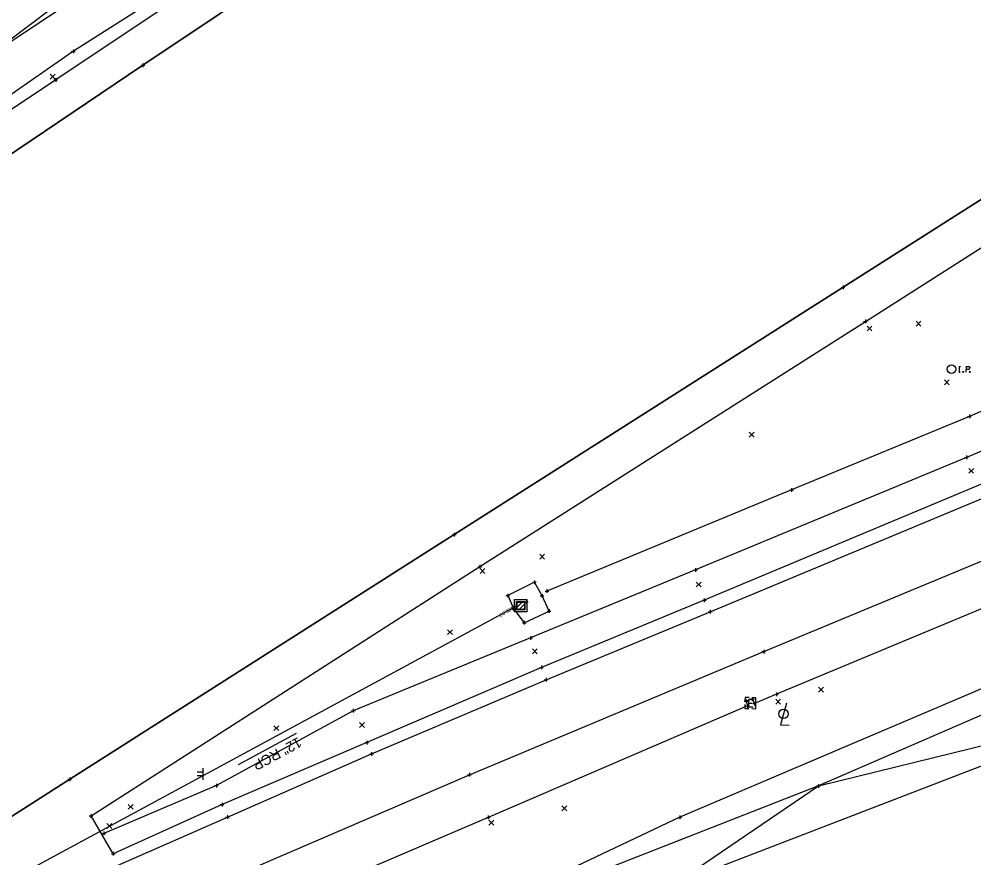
# Model space of a CAD drawing. Extents: x 142461 to 147261, y 511126 to 514697.
# Drawn here: x 144403.5 to 144664.8, y 512765.9 to 512995.5 of the extents above; entities that cross this region are included whole.
import ezdxf

# ---------------------------------------------------------------- set-up
doc = ezdxf.new("R2010")
doc.units = 0
for name, color, linetype in [('DR_X_Cells', 7, 'Continuous'), ('DR_X_Ditch', 7, 'Continuous'), ('DR_X_Elev_Flow', 7, 'Continuous'), ('DR_X_Storm_Sewer', 7, 'Continuous'), ('DR_X_Text', 7, 'Continuous'), ('GK_Drainage_Nodes', 7, 'Continuous'), ('LT_X_Poles', 7, 'Continuous'), ('PM_X_Surveyed_Line', 7, 'Continuous'), ('PV_X_EOP', 7, 'Continuous'), ('PV_X_Shoulder', 7, 'Continuous'), ('RD_X_Concrete_Pad', 7, 'Continuous'), ('RD_X_Fence', 7, 'Continuous'), ('SC_Scratch1', 7, 'Continuous'), ('SN_X_Public', 7, 'Continuous'), ('SV_P_Mon_Cells_Set', 7, 'Continuous'), ('SV_X_Original_Ground', 7, 'Continuous'), ('SV_X_Random_Point', 7, 'Continuous'), ('SV_X_Shot_Marker', 7, 'Continuous'), ('SV_X_Toe_of_Slope', 7, 'Continuous'), ('SV_X_Top_of_Bank', 7, 'Continuous'), ('UT_X_Electric_Cells', 7, 'Continuous'), ('VG_X_Tree_Line_Lt', 7, 'Continuous'), ('VG_X_Tree_Line_Rt', 7, 'Continuous')]:
    doc.layers.add(name, color=color, linetype=linetype)

msp = doc.modelspace()

# ---------------------------------------------------------------- linework, layer by layer
at = {"layer": 'DR_X_Cells'}
for p, q in [((144539.58, 512834.31), (144541.34, 512836.07)), ((144539.58, 512835.44), (144540.21, 512836.07)), ((144540.18, 512833.78), (144541.87, 512835.47)), ((144541.31, 512833.78), (144541.87, 512834.34))]:
    msp.add_line(p, q, dxfattribs=at)
for points in [[(144539.06, 512836.59), (144542.39, 512836.59), (144542.39, 512833.26), (144539.06, 512833.26)], [(144539.58, 512836.07), (144541.87, 512836.07), (144541.87, 512833.78), (144539.58, 512833.78)], [(144539.73, 512835.92), (144541.73, 512835.92), (144541.73, 512833.92), (144539.73, 512833.92)]]:
    msp.add_lwpolyline(points, close=True, dxfattribs=at)
at = {"layer": 'DR_X_Ditch'}
msp.add_lwpolyline([(144155.19, 512824.55), (144192.53, 512847.33), (144223.15, 512869.62), (144254.62, 512891.25), (144280.41, 512905.71), (144318.49, 512934.86), (144358.21, 512961.23), (144398.77, 512988.26), (144440.87, 513020.08), (144475.09, 513048.33), (144506.87, 513067.96), (144540.61, 513089.99), (144584.43, 513110.27), (144621.43, 513136.23), (144661.42, 513162.19), (144708.91, 513198.2), (144729.29, 513226.26), (144727.57, 513229.5), (144738.49, 513243.53), (144758.32, 513273.99)], dxfattribs=at)
at = {"layer": 'DR_X_Elev_Flow'}
for p, q in [((144541.79, 512836.03), (144542.79, 512836.03)), ((144542.29, 512836.53), (144542.29, 512835.53)), ((144542.29, 512836.03), (144542.29, 512836.03))]:
    msp.add_line(p, q, dxfattribs=at)
at = {"layer": 'DR_X_Storm_Sewer'}
msp.add_line((144539.42, 512834.67), (144405.18, 512762.11), dxfattribs=at)
at = {"layer": 'DR_X_Text'}
msp.add_line((144463.5, 512791.48), (144479.38, 512800.06), dxfattribs=at)
at = {"layer": 'GK_Drainage_Nodes'}
for p, q in [((144539.73, 512834.92), (144539.73, 512834.92)), ((144540.73, 512836.59), (144540.73, 512836.59)), ((144540.73, 512835.92), (144540.73, 512835.92)), ((144540.73, 512834.92), (144540.73, 512834.92)), ((144540.73, 512834.92), (144540.73, 512834.92)), ((144540.73, 512834.92), (144540.73, 512834.92)), ((144541.73, 512834.92), (144541.73, 512834.92)), ((144540.73, 512833.92), (144540.73, 512833.92)), ((144540.73, 512833.26), (144540.73, 512833.26))]:
    msp.add_line(p, q, dxfattribs=at)
at = {"layer": 'LT_X_Poles'}
msp.add_lwpolyline([(144613.47, 512808.27), (144611.84, 512802.3), (144614.2, 512802.27)], dxfattribs=at)
msp.add_circle((144612.66, 512805.32), 1.3, dxfattribs=at)
at = {"layer": 'PM_X_Surveyed_Line'}
for points in [[(145244.8, 513598.91), (145189.1, 513544.15), (145118.95, 513483.86), (145022.54, 513402.94), (144981.98, 513369.93), (144853.86, 513268.93), (144843.13, 513260.73), (144805.16, 513232.38), (144766.25, 513204.67), (144725.33, 513176.3), (144684.91, 513148.47), (144644.29, 513120.74), (144603.48, 513093.63), (144562.1, 513066.23), (144520.96, 513039), (144479.14, 513010.91), (144437.33, 512982.92), (144395.18, 512954.5), (144353.44, 512926.48), (144318.54, 512903.34), (144276.1, 512875.34), (144232.02, 512845.98), (144188.92, 512817.39), (144145.08, 512788.07)], [(144079.63, 512572.09), (144161.19, 512623.62), (144232.68, 512669.39), (144303.71, 512715.03), (144372.67, 512758.92), (144417.33, 512787.4), (144522.55, 512854.42), (144628.96, 512922.1), (144693.88, 512963.42), (144795.96, 513028.33), (144851.81, 513063.86), (144912.86, 513102.61), (144997.35, 513156.18), (145071.95, 513203.81), (145158.73, 513259.05)], [(144161.19, 512623.62), (144234.91, 512664.76), (144308.58, 512704.75), (144382.31, 512742.08), (144431.43, 512764.26), (144460.46, 512777.08), (144499.91, 512794.34), (144547.7, 512814.68), (144592.59, 512833.3), (144667.23, 512864.35), (144709.98, 512882.09), (144731.76, 512891.11), (144777.76, 512910.35), (144847.49, 512940.98), (144877.97, 512956.57), (144906.17, 512973.31), (144970.66, 513014.86), (145008.54, 513039.23), (145047.45, 513063.87), (145126.17, 513113.66), (145208.14, 513166.05), (145269.39, 513204.92)], [(144107.76, 512571.5), (144171, 512608.92), (144233.75, 512643.91), (144295.17, 512677.9), (144371.33, 512718.45), (144406.15, 512735.4), (144436.98, 512749.5), (144470.36, 512764.31), (144526.68, 512788.67), (144607.27, 512822.36), (144672.99, 512849.66), (144737.98, 512876.7), (144783.51, 512895.57), (144854.72, 512926.92), (144917.44, 512958.12), (144951.07, 512971.35), (144954.37, 512973.11)]]:
    msp.add_lwpolyline(points, dxfattribs=at)
at = {"layer": 'PV_X_EOP'}
for p, q in [((144490.96, 513030.72), (144413.5, 512978.9)), ((144413.5, 512978.9), (144329.88, 512923)), ((144678.33, 512838.89), (144610.7, 512810.67)), ((144610.7, 512810.67), (144604.72, 512808.14)), ((144604.13, 512809.39), (144602.41, 512808.77)), ((144602.41, 512808.77), (144602.81, 512807.48)), ((144604.72, 512808.14), (144604.13, 512809.39)), ((144602.81, 512807.48), (144531.86, 512776.95)), ((144531.86, 512776.95), (144475.53, 512752.94))]:
    msp.add_line(p, q, dxfattribs=at)
for points in [[(144423.14, 512777.38), (144529.59, 512845.63), (144635.07, 512912.79), (144699.77, 512953.97), (144801.25, 513018.67), (144857.84, 513054.39), (144918.27, 513092.86), (145002.41, 513146.27), (145077.85, 513194.39), (145164.32, 513249.25)], [(144911.02, 512977.55), (144906.51, 512974.41), (144900.33, 512983.57), (144872.27, 512967.78), (144841.71, 512952.09), (144773.16, 512922.36), (144725.8, 512902.13), (144705.18, 512893.45), (144708.57, 512885.5), (144665.93, 512867.84), (144590.97, 512836.44), (144546.42, 512818.03), (144498.61, 512797.46), (144459.01, 512780.5), (144429.23, 512767.01), (144423.14, 512777.38)]]:
    msp.add_lwpolyline(points, dxfattribs=at)
at = {"layer": 'PV_X_Shoulder'}
msp.add_lwpolyline([(144705.18, 512893.45), (144662.72, 512875.53), (144588.59, 512844.72), (144543.46, 512826.1), (144494.9, 512806.19), (144457.46, 512785.68), (144426.6, 512772.57)], dxfattribs=at)
at = {"layer": 'RD_X_Concrete_Pad'}
msp.add_lwpolyline([(144541.72, 512830.26), (144548.49, 512833.47), (144546.57, 512837.62), (144544.51, 512841.36), (144537.19, 512837.72), (144538.83, 512834)], close=True, dxfattribs=at)
at = {"layer": 'RD_X_Fence'}
msp.add_lwpolyline([(143478.94, 512019.34), (143711.38, 512177.16), (144427.62, 512645.69), (144477.47, 512681.98), (144582.58, 512758.57), (144706.18, 512806.24), (144763.41, 512828.73), (144839.36, 512854.89), (144928.89, 512885.13), (144926.13, 512699.9), (144921.71, 512476.45), (144997.12, 512524.34), (145097.9, 512588.02), (145394.3, 512776.52), (145562.04, 512882.95), (145736.06, 512993.23), (145625.27, 513165.45), (145520.47, 513331.41), (145754.83, 513482.5), (146985.53, 514272.72), (147146.04, 514395.19)], dxfattribs=at)
at = {"layer": 'SN_X_Public'}
for p, q in [((144453.78, 512790.45), (144453.78, 512787.25)), ((144453.78, 512789.33), (144452.18, 512789.33)), ((144453.78, 512788.37), (144452.18, 512788.37)), ((144453.78, 512788.85), (144453.78, 512788.85))]:
    msp.add_line(p, q, dxfattribs=at)
at = {"layer": 'SV_P_Mon_Cells_Set'}
for p, q in [((144660.66, 512900.46), (144661.06, 512900.46)), ((144660.84, 512898.86), (144660.86, 512900.46)), ((144662.69, 512899.68), (144663.34, 512899.67)), ((144660.64, 512898.86), (144661.04, 512898.86))]:
    msp.add_line(p, q, dxfattribs=at)
msp.add_lwpolyline([(144662.68, 512898.84), (144662.7, 512900.44), (144663.35, 512900.44)], dxfattribs=at)
for centre, radius in [((144658.65, 512899.69), 1.2), ((144661.81, 512898.96), 0.14), ((144663.65, 512898.94), 0.14)]:
    msp.add_circle(centre, radius, dxfattribs=at)
for points in [[(144663.34, 512899.67), (144663.41, 512899.68), (144663.59, 512899.78), (144663.66, 512899.96), (144663.67, 512900.05), (144663.67, 512900.05), (144663.67, 512900.05)], [(144663.35, 512900.44), (144663.48, 512900.4), (144663.61, 512900.29), (144663.66, 512900.15), (144663.67, 512900.05)]]:
    msp.add_open_spline(points, degree=2, dxfattribs=at)
at = {"layer": 'SV_X_Original_Ground'}
for points in [[(145158.73, 513259.05), (145071.95, 513203.81), (144997.35, 513156.18), (144912.86, 513102.61), (144851.81, 513063.86), (144795.96, 513028.33), (144693.88, 512963.42), (144628.96, 512922.1), (144522.55, 512854.42), (144417.33, 512787.4), (144372.67, 512758.92), (144303.71, 512715.03), (144232.68, 512669.39), (144161.19, 512623.62), (144079.63, 512572.09)], [(144145.08, 512788.07), (144188.92, 512817.39), (144232.02, 512845.98), (144276.1, 512875.34), (144318.54, 512903.34), (144353.44, 512926.48), (144395.18, 512954.5), (144437.33, 512982.92), (144479.14, 513010.91), (144520.96, 513039), (144562.1, 513066.23), (144603.48, 513093.63), (144644.29, 513120.74), (144684.91, 513148.47), (144725.33, 513176.3), (144766.25, 513204.67), (144805.16, 513232.38)], [(144146.46, 512461.37), (144182.31, 512479.61), (144214, 512505.32), (144287, 512560.13), (144347.93, 512601.69), (144364.84, 512611.91), (144427.62, 512645.69), (144477.47, 512681.98), (144514.41, 512743.19), (144582.58, 512758.57), (144622.22, 512785.58), (144706.18, 512806.24)]]:
    msp.add_lwpolyline(points, dxfattribs=at)
at = {"layer": 'SV_X_Random_Point'}
for p, q in [((144411.97, 512980.45), (144413.29, 512979.11)), ((144411.96, 512979.12), (144413.3, 512980.44)), ((144648.95, 512911.51), (144650.28, 512912.84)), ((144648.95, 512912.84), (144650.28, 512911.51)), ((144635.51, 512910.17), (144636.86, 512911.49)), ((144635.52, 512911.51), (144636.84, 512910.16)), ((144656.71, 512895.42), (144658.04, 512896.76)), ((144656.71, 512896.76), (144658.04, 512895.42)), ((144603.3, 512881.12), (144604.64, 512882.46)), ((144603.3, 512882.46), (144604.64, 512881.12)), ((144663.37, 512871.19), (144664.72, 512872.51)), ((144663.38, 512872.53), (144664.7, 512871.18)), ((144545.93, 512847.66), (144547.26, 512849)), ((144545.93, 512849), (144547.26, 512847.66)), ((144529.61, 512843.78), (144530.96, 512845.1)), ((144529.62, 512845.12), (144530.94, 512843.77)), ((144588.77, 512840.09), (144590.12, 512841.41)), ((144588.79, 512841.42), (144590.1, 512840.07)), ((144520.72, 512827.04), (144522.05, 512828.37)), ((144520.72, 512828.37), (144522.05, 512827.04)), ((144543.93, 512821.8), (144545.28, 512823.12)), ((144543.94, 512823.13), (144545.26, 512821.79)), ((144622.25, 512811.27), (144623.58, 512812.6)), ((144622.25, 512812.6), (144623.58, 512811.27)), ((144610.52, 512808.02), (144611.87, 512809.35)), ((144610.54, 512809.36), (144611.86, 512808.01)), ((144496.61, 512801.63), (144497.96, 512802.95)), ((144496.63, 512802.96), (144497.95, 512801.61)), ((144473.16, 512800.74), (144474.5, 512802.07)), ((144473.16, 512802.07), (144474.5, 512800.74)), ((144433.31, 512779.2), (144434.64, 512780.53)), ((144433.31, 512780.53), (144434.64, 512779.2)), ((144552, 512778.77), (144553.34, 512780.11)), ((144552, 512780.11), (144553.34, 512778.77)), ((144427.47, 512773.97), (144428.81, 512775.29)), ((144427.48, 512775.31), (144428.8, 512773.96)), ((144532, 512774.88), (144533.35, 512776.2)), ((144532.02, 512776.21), (144533.34, 512774.86))]:
    msp.add_line(p, q, dxfattribs=at)
at = {"layer": 'SV_X_Shot_Marker'}
for p, q in [((144417.81, 512986.73), (144418.81, 512986.73)), ((144418.31, 512987.23), (144418.31, 512986.23)), ((144418.31, 512986.73), (144418.31, 512986.73)), ((144437.33, 512983.42), (144437.33, 512982.42)), ((144436.83, 512982.92), (144437.83, 512982.92)), ((144437.33, 512982.92), (144437.33, 512982.92)), ((144413, 512978.91), (144414, 512978.9)), ((144413.51, 512979.4), (144413.5, 512978.4)), ((144413.5, 512978.9), (144413.5, 512978.9)), ((144628.46, 512922.1), (144629.46, 512922.09)), ((144628.96, 512922.6), (144628.95, 512921.6)), ((144628.96, 512922.1), (144628.96, 512922.1)), ((144634.57, 512912.79), (144635.57, 512912.78)), ((144635.08, 512913.29), (144635.07, 512912.29)), ((144635.07, 512912.79), (144635.07, 512912.79)), ((144663.06, 512886.77), (144664.06, 512886.77)), ((144663.56, 512887.27), (144663.56, 512886.27)), ((144663.56, 512886.77), (144663.56, 512886.77)), ((144662.73, 512876.03), (144662.72, 512875.03)), ((144662.22, 512875.54), (144663.22, 512875.53)), ((144662.72, 512875.53), (144662.72, 512875.53)), ((144614.36, 512866.63), (144615.36, 512866.63)), ((144614.86, 512867.13), (144614.86, 512866.13)), ((144614.86, 512866.63), (144614.86, 512866.63)), ((144522.05, 512854.43), (144523.05, 512854.42)), ((144522.55, 512854.92), (144522.54, 512853.92)), ((144522.55, 512854.42), (144522.55, 512854.42)), ((144529.09, 512845.63), (144530.09, 512845.62)), ((144529.59, 512846.13), (144529.58, 512845.13)), ((144529.59, 512845.63), (144529.59, 512845.63)), ((144588.09, 512844.73), (144589.09, 512844.72)), ((144588.59, 512845.22), (144588.58, 512844.22)), ((144588.59, 512844.72), (144588.59, 512844.72)), ((144544.01, 512841.36), (144545.01, 512841.36)), ((144544.51, 512841.86), (144544.51, 512840.86)), ((144544.51, 512841.36), (144544.51, 512841.36)), ((144547.92, 512839.43), (144547.92, 512838.43)), ((144536.69, 512837.72), (144537.69, 512837.72)), ((144537.19, 512838.22), (144537.19, 512837.22)), ((144537.19, 512837.72), (144537.19, 512837.72)), ((144546.07, 512837.62), (144547.07, 512837.62)), ((144546.57, 512838.12), (144546.57, 512837.12)), ((144546.57, 512837.62), (144546.57, 512837.62)), ((144547.42, 512838.93), (144548.42, 512838.93)), ((144547.92, 512838.93), (144547.92, 512838.93)), ((144590.97, 512836.94), (144590.96, 512835.94)), ((144538.83, 512834.5), (144538.83, 512833.5)), ((144538.92, 512834.67), (144539.92, 512834.67)), ((144539.42, 512835.17), (144539.42, 512834.17)), ((144539.42, 512834.67), (144539.42, 512834.67)), ((144590.47, 512836.45), (144591.47, 512836.44)), ((144590.97, 512836.44), (144590.97, 512836.44)), ((144538.33, 512834), (144539.33, 512834)), ((144538.83, 512834), (144538.83, 512834)), ((144547.99, 512833.47), (144548.99, 512833.47)), ((144548.49, 512833.97), (144548.49, 512832.97)), ((144548.49, 512833.47), (144548.49, 512833.47)), ((144592.09, 512833.31), (144593.09, 512833.29)), ((144592.59, 512833.8), (144592.58, 512832.8)), ((144592.59, 512833.3), (144592.59, 512833.3)), ((144541.22, 512830.26), (144542.22, 512830.26)), ((144541.72, 512830.76), (144541.72, 512829.76)), ((144541.72, 512830.26), (144541.72, 512830.26)), ((144543.47, 512826.6), (144543.46, 512825.6)), ((144542.96, 512826.1), (144543.96, 512826.09)), ((144543.46, 512826.1), (144543.46, 512826.1)), ((144606.77, 512822.36), (144607.77, 512822.35)), ((144607.27, 512822.86), (144607.26, 512821.86)), ((144607.27, 512822.36), (144607.27, 512822.36)), ((144546.43, 512818.53), (144546.42, 512817.53)), ((144545.92, 512818.04), (144546.92, 512818.02)), ((144546.42, 512818.03), (144546.42, 512818.03)), ((144547.2, 512814.69), (144548.2, 512814.68)), ((144547.71, 512815.18), (144547.7, 512814.18)), ((144547.7, 512814.68), (144547.7, 512814.68)), ((144610.2, 512810.67), (144611.2, 512810.66)), ((144610.71, 512811.17), (144610.7, 512810.17)), ((144610.7, 512810.67), (144610.7, 512810.67)), ((144601.91, 512808.77), (144602.91, 512808.76)), ((144602.42, 512809.27), (144602.41, 512808.27)), ((144602.41, 512808.77), (144602.41, 512808.77)), ((144603.63, 512809.39), (144604.63, 512809.38)), ((144604.13, 512809.89), (144604.12, 512808.89)), ((144604.13, 512809.39), (144604.13, 512809.39)), ((144604.22, 512808.15), (144605.22, 512808.14)), ((144604.72, 512808.64), (144604.71, 512807.64)), ((144604.72, 512808.14), (144604.72, 512808.14)), ((144494.4, 512806.2), (144495.4, 512806.19)), ((144494.91, 512806.69), (144494.9, 512805.69)), ((144494.9, 512806.19), (144494.9, 512806.19)), ((144602.31, 512807.48), (144603.31, 512807.47)), ((144602.82, 512807.98), (144602.81, 512806.98)), ((144602.81, 512807.48), (144602.81, 512807.48)), ((144498.62, 512797.96), (144498.6, 512796.96)), ((144498.11, 512797.46), (144499.11, 512797.45)), ((144498.61, 512797.46), (144498.61, 512797.46)), ((144499.41, 512794.35), (144500.41, 512794.34)), ((144499.91, 512794.84), (144499.9, 512793.84)), ((144499.91, 512794.34), (144499.91, 512794.34)), ((144416.83, 512787.41), (144417.83, 512787.4)), ((144417.33, 512787.9), (144417.32, 512786.9)), ((144417.33, 512787.4), (144417.33, 512787.4)), ((144526.18, 512788.67), (144527.18, 512788.66)), ((144526.68, 512789.17), (144526.67, 512788.17)), ((144526.68, 512788.67), (144526.68, 512788.67)), ((144456.96, 512785.68), (144457.96, 512785.67)), ((144457.46, 512786.18), (144457.45, 512785.18)), ((144457.46, 512785.68), (144457.46, 512785.68)), ((144621.72, 512785.58), (144622.72, 512785.58)), ((144622.22, 512786.08), (144622.22, 512785.08)), ((144622.22, 512785.58), (144622.22, 512785.58)), ((144458.51, 512780.51), (144459.51, 512780.5)), ((144459.01, 512781), (144459, 512780)), ((144459.01, 512780.5), (144459.01, 512780.5)), ((144422.64, 512777.38), (144423.64, 512777.37)), ((144423.14, 512777.88), (144423.13, 512776.88)), ((144423.14, 512777.38), (144423.14, 512777.38)), ((144459.96, 512777.08), (144460.96, 512777.07)), ((144460.46, 512777.58), (144460.45, 512776.58)), ((144460.46, 512777.08), (144460.46, 512777.08)), ((144531.36, 512776.95), (144532.36, 512776.94)), ((144531.87, 512777.45), (144531.86, 512776.45)), ((144531.86, 512776.95), (144531.86, 512776.95)), ((144583.76, 512777), (144584.76, 512776.99)), ((144584.27, 512777.5), (144584.26, 512776.5)), ((144584.26, 512777), (144584.26, 512777)), ((144426.1, 512772.57), (144427.1, 512772.56)), ((144426.61, 512773.07), (144426.6, 512772.07)), ((144426.6, 512772.57), (144426.6, 512772.57)), ((144428.73, 512767.01), (144429.73, 512767)), ((144429.24, 512767.51), (144429.23, 512766.51)), ((144429.23, 512767.01), (144429.23, 512767.01))]:
    msp.add_line(p, q, dxfattribs=at)
at = {"layer": 'SV_X_Toe_of_Slope'}
msp.add_lwpolyline([(145536.33, 513468.51), (145487.34, 513431.87), (145445.96, 513398.71), (145400.54, 513359.53), (145354.59, 513321.64), (145305.79, 513280.24), (145266.24, 513246.77), (145228.58, 513220.65), (145175.08, 513189.66), (145126.31, 513155.94), (145081.98, 513127.67), (145034.97, 513097.1), (144983.36, 513063.49), (144934.41, 513028.84), (144889.77, 512994.77), (144833.63, 512962.42), (144772.97, 512934.59), (144716.73, 512910.04), (144663.56, 512886.77), (144614.86, 512866.63), (144547.92, 512838.93)], dxfattribs=at)
at = {"layer": 'SV_X_Top_of_Bank'}
for points in [[(144938.7, 513352.73), (144903.82, 513325.51), (144869.31, 513299.61), (144834.32, 513271.97), (144798.6, 513244.63), (144760.27, 513217.79), (144723.38, 513192.87), (144685.94, 513168.03), (144649.73, 513141.54), (144613.86, 513117.07), (144574.64, 513090.25), (144534.95, 513065.21), (144496.59, 513038.93), (144457.47, 513011.69), (144418.31, 512986.73), (144376.29, 512957.57), (144335.22, 512930.35), (144295.66, 512903.81), (144255.35, 512877.84), (144213.89, 512852), (144187.53, 512836.11), (144149.1, 512812.16)], [(144733.96, 512831.9), (144682.77, 512811.9), (144622.22, 512785.58), (144559.34, 512760.99), (144514.41, 512743.19), (144445.8, 512704.27), (144422.79, 512686.96), (144404.36, 512674.95), (144403.17, 512671), (144396.75, 512657.34), (144383.89, 512640.78), (144355.33, 512621.72), (144335.88, 512616.13), (144292.97, 512579.83), (144267.67, 512559.63), (144244.44, 512540.09), (144210.27, 512518.05), (144173.39, 512489.57), (144164.15, 512481.04)]]:
    msp.add_lwpolyline(points, dxfattribs=at)
at = {"layer": 'UT_X_Electric_Cells'}
for p, q in [((144603.11, 512808.26), (144604.11, 512808.25)), ((144603.61, 512808.25), (144603.61, 512808.25))]:
    msp.add_line(p, q, dxfattribs=at)
for points in [[(144603.23, 512809.76), (144602.13, 512809.77), (144602.11, 512808.67)], [(144604.37, 512809.24), (144603.12, 512809.26), (144603.1, 512807.26), (144604.35, 512807.24)], [(144605.11, 512808.64), (144605.13, 512809.74), (144604.03, 512809.75)], [(144602.11, 512807.87), (144602.1, 512806.77), (144603.2, 512806.76)], [(144604, 512806.75), (144605.1, 512806.74), (144605.11, 512807.84)]]:
    msp.add_lwpolyline(points, dxfattribs=at)
at = {"layer": 'VG_X_Tree_Line_Lt'}
msp.add_lwpolyline([(144949.64, 513970.2), (144940.67, 513403.38), (144869.27, 513342.8), (144835.43, 513285.24), (144755.87, 513265.97), (144717.47, 513211.11), (144425.23, 513005.37), (144089.54, 512783), (144041.9, 512744.84), (143854.58, 512619.22), (143367, 512303.84)], dxfattribs=at)
at = {"layer": 'VG_X_Tree_Line_Rt'}
msp.add_lwpolyline([(144921.71, 512476.45), (144926.13, 512699.9), (144928.89, 512885.13), (144828.22, 512889.46), (144750.74, 512847.64), (144698.78, 512825.75), (144584.26, 512777), (144464.04, 512719.97), (144375.77, 512695.09), (143711.38, 512177.16), (143478.94, 512019.34)], dxfattribs=at)

# ---------------------------------------------------------------- texts
at = {"layer": 'DR_X_Text'}
msp.add_text('12" RCP', height=2.8, rotation=208.3903, dxfattribs=at).set_placement((144479.81, 512799.04))
at = {"layer": 'SC_Scratch1'}
msp.add_text("1108.97'", height=1, rotation=208.3903, dxfattribs=at).set_placement((144539.18, 512835.11))

doc.saveas('drawing.dxf')
